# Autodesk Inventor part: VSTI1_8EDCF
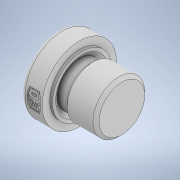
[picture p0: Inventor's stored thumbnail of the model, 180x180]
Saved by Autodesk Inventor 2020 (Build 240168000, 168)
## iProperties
Created: 2019-12
Part Number: VSTI1_8EDCF
Material: Generico
Description: STEP AP203
Document SubType Name: Modeling
Designer: carlo
Density: 1 g/cm^3
Appearance: Default
DataBaseUnit: MM
Title: p:/temp/worker_146/temp/exporttempdir_1896_251_0Pq7q/format_0/EO Verschluss-Stopfen fuer Einschraubloecher VSTI1_8EDCF.stp
Revision Number: NONE
Sending System: PARTsolutions
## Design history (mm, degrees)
feature "_EO Verschluss-Stopfen fuer Einschraubloecher VSTI1_8EDCF"
node "Piano di lavoro1"
node "Piano di lavoro2"
node "Asse di lavoro1"
node "Solido1"
other parameters: "d0" = 0, "d1" = 0
